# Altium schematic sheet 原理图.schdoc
size 292 x 204 mm; Device: A_A4; Symbol: A_A4; Name: A_A4; @Project Name: MYNOVA-射频管家; REV: 1.0; Date: 2024/03/05; Sheet: 1/1; Draw By: Tomosawa; Company: MYNOVA; Convert to PCB: yes; Add into BOM: yes
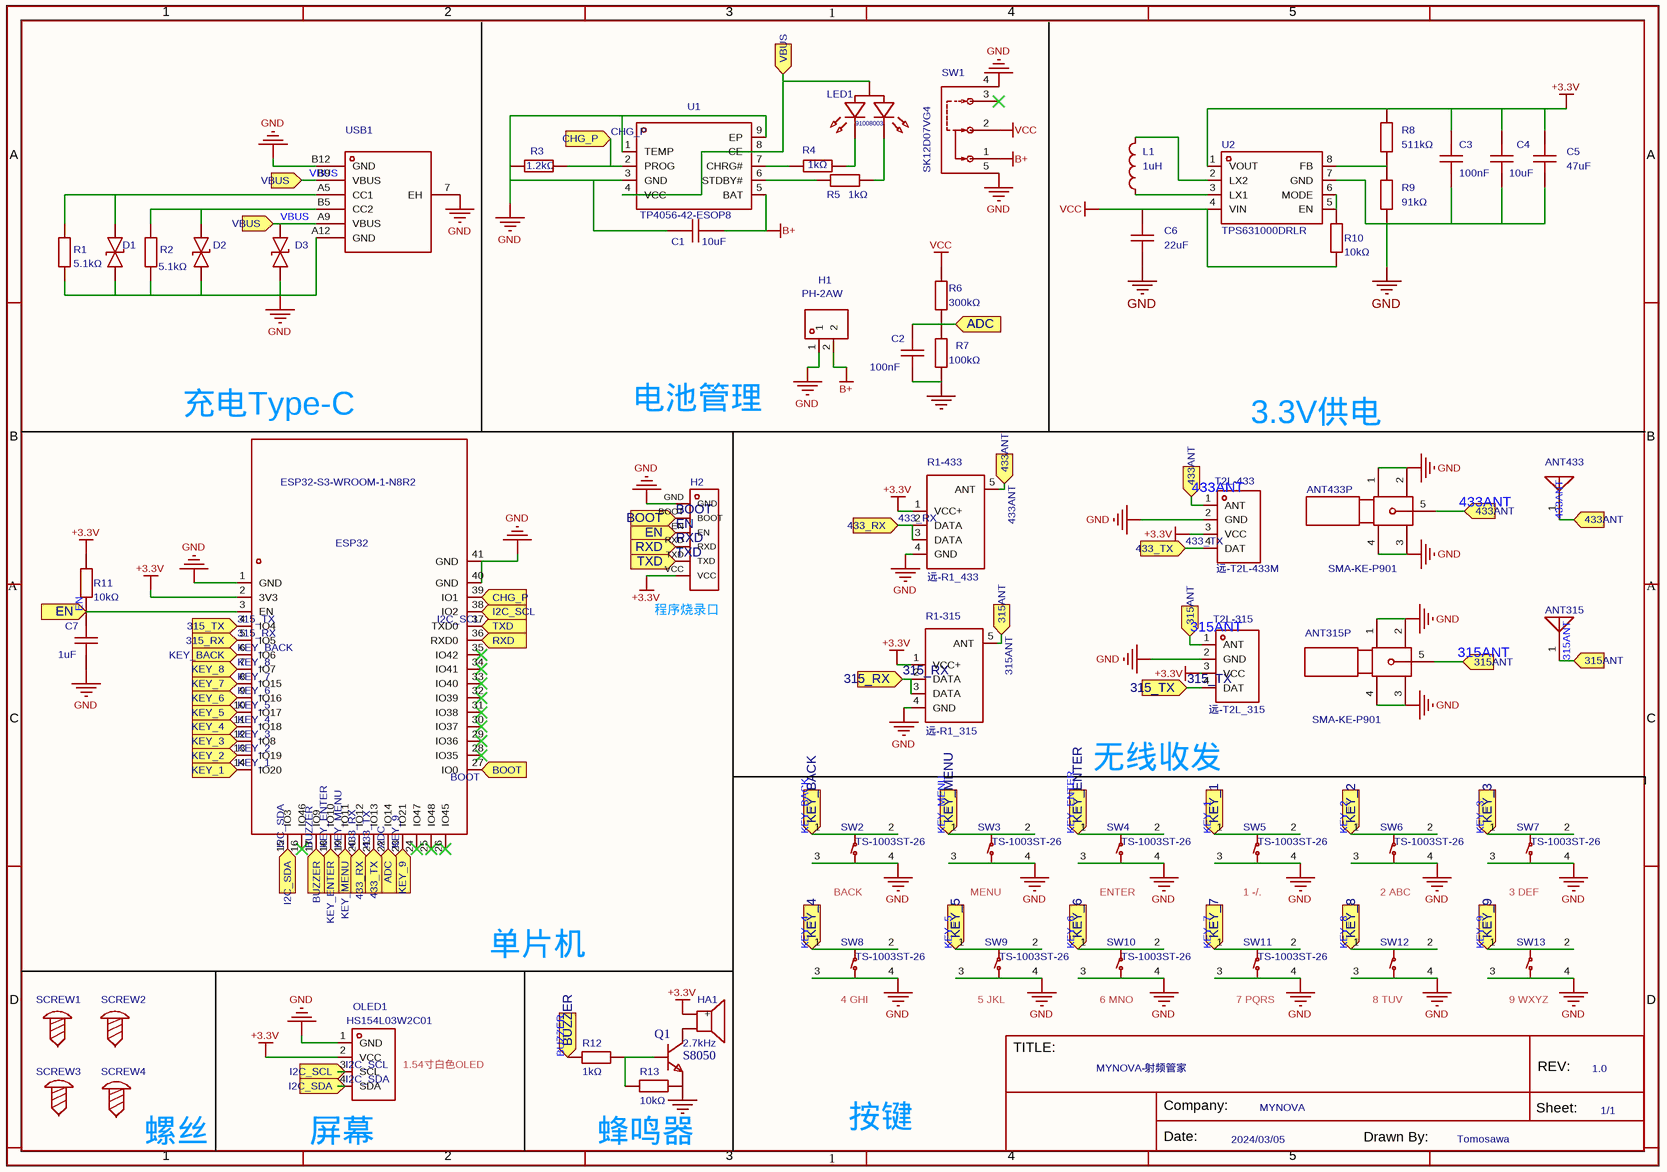
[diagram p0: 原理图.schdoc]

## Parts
ANT315  (no value)  [SMD-ANT-315]
ANT315P  SMA-KE-P901  [SMA-TH_SMA-KE-P901]
ANT433  (no value)  [SMD-ANT-433]
ANT433P  SMA-KE-P901  [SMA-TH_SMA-KE-P901]
C1  10uF  [C0603]
C2  100nF  [C0603]
C3  100nF  [C0603]
C4  10uF  [C0603]
C5  47uF  [C0603]
C6  22uF  [C0603]
C7  1uF  [C0603]
D1  LESD5D5.0CT1G  [SOD-523_L1.2-W0.8-LS1.6-BI]  (value not drawn)
D2  LESD5D5.0CT1G  [SOD-523_L1.2-W0.8-LS1.6-BI]  (value not drawn)
D3  LESD5D5.0CT1G  [SOD-523_L1.2-W0.8-LS1.6-BI]  (value not drawn)
ESP32  ESP32-S3-WROOM-1-N8R2  [WIRELM-SMD_ESP32-S3-WROOM-1]
H1  PH-2AW  [CONN-TH_PH-2AW_C2908634]
H2  (no value)  [6PIN-2MM-UART]
HA1  2.7kHz  [BUZ-TH_BD9.0-P5.00-D0.6-FD]
L1  1uH  [L1008]
LED1  91008003  [LED-TH_3P-BD3.8-P2.54-BI]
OLED1  HS154L03W2C01  [OLED-TH_-4P-L42.4-W38.0-P2.54]
Q1  S8050  [SOT-23-3_L2.9-W1.3-P1.90-LS2.4-BR]
R1  5.1kΩ  [R0603]
R1-315  远-R1_315  [COMM-SMD_YUAN-R1-315]
R1-433  远-R1_433  [COMM-SMD_YUAN-R1-433]
R2  5.1kΩ  [R0603]
R3  1.2kΩ  [R0603]
R4  1kΩ  [R0603]
R5  1kΩ  [R0603]
R6  300kΩ  [R0603]
R7  100kΩ  [R0603]
R8  511kΩ  [R0603]
R9  91kΩ  [R0603]
R10  10kΩ  [R0603]
R11  10kΩ  [R0603]
R12  1kΩ  [R0603]
R13  10kΩ  [R0603]
SCREW1  (no value)  [M2螺丝]
SCREW2  (no value)  [M2螺丝]
SCREW3  (no value)  [M2螺丝]
SCREW4  (no value)  [M2螺丝]
SW1  SK12D07VG4  [SW-TH_SK12D07VG4]
SW2  TS-1003ST-26  [SW-SMD-1212KEY]
SW3  TS-1003ST-26  [SW-SMD-1212KEY]
SW4  TS-1003ST-26  [SW-SMD-1212KEY]
SW5  TS-1003ST-26  [SW-SMD-1212KEY]
SW6  TS-1003ST-26  [SW-SMD-1212KEY]
SW7  TS-1003ST-26  [SW-SMD-1212KEY]
SW8  TS-1003ST-26  [SW-SMD-1212KEY]
SW9  TS-1003ST-26  [SW-SMD-1212KEY]
SW10  TS-1003ST-26  [SW-SMD-1212KEY]
SW11  TS-1003ST-26  [SW-SMD-1212KEY]
SW12  TS-1003ST-26  [SW-SMD-1212KEY]  (value not drawn)
SW13  TS-1003ST-26  [SW-SMD-1212KEY]  (value not drawn)
T2L-315  远-T2L_315  [WIRELM-SMD_L10.5-W8.3-P2.54]
T2L-433  远-T2L-433M  [WIRELM-SMD_L10.5-W8.3-P2.54]
U1  TP4056-42-ESOP8  [ESOP-8_L4.9-W3.9-P1.27-LS6.0-BL-EP]
U2  TPS631000DRLR  [SOT-583-8_L2.1-W1.2-P0.50-LS1.6-BL]
USB1  TYPE-C 6P(073)  [TYPE-C-SMD_TYPE-C-6P]  (value not drawn)

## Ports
315_RX (in), 315_TX (in), 315ANT (in), 433_RX (in), 433_TX (in), 433ANT (in), ADC (in), BOOT (in), BUZZER (in), CHG_P (in), EN (in), I2C_SCL (in), I2C_SDA (in), KEY_1 (in), KEY_2 (in), KEY_3 (in), KEY_4 (in), KEY_5 (in), KEY_6 (in), KEY_7 (in), KEY_8 (in), KEY_9 (in), KEY_BACK (in), KEY_ENTER (in), KEY_MENU (in), RXD (in), TXD (in), VBUS (in)

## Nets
+3.3V: C3.2 C4.2 C5.2 ESP32.2(3V3) H2.VCC HA1.1(+) OLED1.2(VCC) R1-315.1(VCC+) R1-433.1(VCC+) R8.2 R11.1 T2L-315.3(VCC) T2L-433.3(VCC) U2.1(VOUT)
B+: C1.1 H1.2 SW1.1 U1.5(BAT)
GND: ANT315P.1 ANT315P.2 ANT315P.3 ANT315P.4 ANT433P.1 ANT433P.2 ANT433P.3 ANT433P.4 C1.2 C2.1 C3.1 C4.1 C5.1 C6.1 C7.1 D1.2 D2.2 D3.2 ESP32.1(GND) ESP32.40(GND) ESP32.41(GND) H1.1 H2.GND OLED1.1(GND) Q1.2(E) R1.2 R1-315.4(GND) R1-433.4(GND) R2.2 R3.1 R7.1 R9.1 R13.2 SW1.4 SW1.5 SW2.3(C) SW2.4(D) SW3.3(C) SW3.4(D) SW4.3(C) SW4.4(D) SW5.3(C) SW5.4(D) SW6.3(C) SW6.4(D) SW7.3(C) SW7.4(D) SW8.3(C) SW8.4(D) SW9.3(C) SW9.4(D) SW10.3(C) SW10.4(D) SW11.3(C) SW11.4(D) SW12.3(C) SW12.4(D) SW13.3(C) SW13.4(D) T2L-315.2(GND) T2L-433.2(GND) U1.1(TEMP) U1.3(GND) U1.9(EP) U2.7(GND) USB1.7(EH) USB1.A12(GND) USB1.B12(GND)
VCC: C6.2 R6.2 R10.2 SW1.2 U2.4(VIN)
315_RX: ESP32.5(IO5) R1-315.2(DATA) R1-315.3(DATA) ; port 315_RX
315_TX: ESP32.4(IO4) T2L-315.4(DAT) ; port 315_TX
315ANT: ANT315.1 ANT315P.5 R1-315.5(ANT) T2L-315.1(ANT) ; port 315ANT
433_RX: ESP32.20(IO12) R1-433.2(DATA) R1-433.3(DATA) ; port 433_RX
433_TX: ESP32.21(IO13) T2L-433.4(DAT) ; port 433_TX
433ANT: ANT433.1 ANT433P.5 R1-433.5(ANT) T2L-433.1(ANT) ; port 433ANT
ADC: C2.2 ESP32.22(IO14) R6.1 R7.2 ; port ADC
BOOT: ESP32.27(IO0) H2.BOOT ; port BOOT
BUZZER: ESP32.17(IO9) R12.1 ; port BUZZER
CHG_P: ESP32.39(IO1) R3.2 U1.2(PROG) ; port CHG_P
EN: C7.2 ESP32.3(EN) H2.EN R11.2 ; port EN
I2C_SCL: ESP32.38(IO2) OLED1.3(SCL) ; port I2C_SCL
I2C_SDA: ESP32.15(IO3) OLED1.4(SDA) ; port I2C_SDA
KEY_1: ESP32.14(IO20) SW5.1(A) SW5.2(B) ; port KEY_1
KEY_2: ESP32.13(IO19) SW6.1(A) SW6.2(B) ; port KEY_2
KEY_3: ESP32.12(IO8) SW7.1(A) SW7.2(B) ; port KEY_3
KEY_4: ESP32.11(IO18) SW8.1(A) SW8.2(B) ; port KEY_4
KEY_5: ESP32.10(IO17) SW9.1(A) SW9.2(B) ; port KEY_5
KEY_6: ESP32.9(IO16) SW10.1(A) SW10.2(B) ; port KEY_6
KEY_7: ESP32.8(IO15) SW11.1(A) SW11.2(B) ; port KEY_7
KEY_8: ESP32.7(IO7) SW12.1(A) SW12.2(B) ; port KEY_8
KEY_9: ESP32.23(IO21) SW13.1(A) SW13.2(B) ; port KEY_9
KEY_BACK: ESP32.6(IO6) SW2.1(A) SW2.2(B) ; port KEY_BACK
KEY_ENTER: ESP32.18(IO10) SW4.1(A) SW4.2(B) ; port KEY_ENTER
KEY_MENU: ESP32.19(IO11) SW3.1(A) SW3.2(B) ; port KEY_MENU
RXD: ESP32.36(RXD0) H2.RXD ; port RXD
TXD: ESP32.37(TXD0) H2.TXD ; port TXD
VBUS: D3.1 LED1.2(K) U1.4(VCC) U1.8(CE) USB1.A9(VBUS) USB1.B9(VBUS) ; port VBUS
NetD1_1: D1.1 R1.1 USB1.A5(CC1)
NetD2_1: D2.1 R2.1 USB1.B5(CC2)
NetHA1_2: HA1.2 Q1.3(C)
NetL1_1: L1.1 U2.3(LX1)
NetL1_2: L1.2 U2.2(LX2)
NetLED1_1: LED1.1(A) R5.1
NetLED1_3: LED1.3(A) R4.1
NetQ1_1: Q1.1(B) R12.2 R13.1
NetR4_2: R4.2 U1.7(CHRG#)
NetR5_2: R5.2 U1.6(STDBY#)
NetR8_1: R8.1 R9.2 U2.8(FB)
NetR10_1: R10.1 U2.5(EN) U2.6(MODE)

Not connected (* = marked no-connect by the designer): ESP32 16(IO46)* 24(IO47)* 25(IO48)* 26(IO45)* 28(IO35)* 29(IO36)* 30(IO37)* 31(IO38)* 32(IO39)* 33(IO40)* 34(IO41)* 35(IO42)*; SCREW1 1; SCREW2 1; SCREW3 1; SCREW4 1; SW1 3*

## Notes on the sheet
- 充电Type-C
- 电池管理
- 3.3V供电
- (near H2) 程序烧录口
- 无线收发
- (near SW2) BACK
- (near SW3) MENU
- (near SW4) ENTER
- (near SW5) 1 -/.
- (near SW6) 2 ABC
- (near SW7) 3 DEF
- 单片机
- (near SW8) 4 GHI
- (near SW9) 5 JKL
- (near SW10) 6 MNO
- (near SW11) 7 PQRS
- (near SW12) 8 TUV
- (near SW13) 9 WXYZ
- (near OLED1) 1.54寸白色OLED
- (near SCREW4) 螺丝
- (near OLED1) 屏幕
- (near R13) 蜂鸣器
- 按键

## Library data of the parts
ANT315 = ANT-315MHz: 315MHz的天线; Manufacturer: DreamLNK(骏晔科技); Manufacturer Part: T16-315M; Connector Type: 板端; Interface Type: 内针; Number of Ports: 1; Interface Diameter: 5.35mm; Frequency-Max: 3GHz; RF Series: RP-SMA; Impedance: 50Ω; Style: 偏脚; Origin Footprint: 433MHZ天线; Convert to PCB: yes; ModelId: 24642a22739b4c8ba708c6c7ad2992f36727c7c5e668472884194f91f9f46558; ModelName: ANT315; ModelTransform: 208.66,1336.26,208.66,-90,90,0,0,-472.44,102.36
ANT315P = SMA-KE-P901: 连接器类型:板端;接口类型:内针;端口数量:1;接口直径:5.35mm;接口长度/高度:-;频率-最大值:3GHz;射频系列:RP-SMA;阻抗:50Ω;样式:偏脚;工作温度范围:-55℃~+125℃;; Manufacturer: DreamLNK(骏晔科技); Origin Footprint: 315MHZ天线; Convert to PCB: yes; ModelId: 7448f774b1b34b0fa378ce7b88059936; ModelTransform: 249.9995,448.818,0,180,0,0,0,192.441,-110.236; Connector Type: 板端; Interface Type: 内针; Number of Ports: 1; Interface Diameter: 5.35mm; Frequency-Max: 3GHz; RF Series: RP-SMA; Impedance: 50Ω; Style: 偏脚
ANT433 = ANT-433MHz: 433MHz的天线; Manufacturer: Vollgo(沃进); Manufacturer Part: VG433SNX39-6W3; Connector Type: 板端; Interface Type: 内针; Number of Ports: 1; Interface Diameter: 5.35mm; Frequency-Max: 3GHz; RF Series: RP-SMA; Impedance: 50Ω; Style: 偏脚; Origin Footprint: 433MHZ天线; Symbol: ANT-315MHz; Convert to PCB: yes; Antenna Type: 弹簧天线; Central Frequency: 433MHz; Peak Gain: 2.5dBi; Polarization Type: 垂直; VSWR: 2; ModelId: 49afb8bdb95845d6999d595e8683600d6727c7c5e668472884194f91f9f46558; ModelName: ANT433; ModelTransform: 228.35,228.35,1452.47,90,0,90,-59.06,0,118.11
ANT433P = SMA-KE-P901: 连接器类型:板端;接口类型:内针;端口数量:1;接口直径:5.35mm;接口长度/高度:-;频率-最大值:3GHz;射频系列:RP-SMA;阻抗:50Ω;样式:偏脚;工作温度范围:-55℃~+125℃;; Manufacturer: DreamLNK(骏晔科技); Origin Footprint: 433MHZ天线; Convert to PCB: yes; ModelId: 7448f774b1b34b0fa378ce7b88059936; ModelTransform: 249.9995,448.818,0,180,0,0,0,192.441,-110.236; Connector Type: 板端; Interface Type: 内针; Number of Ports: 1; Interface Diameter: 5.35mm; Frequency-Max: 3GHz; RF Series: RP-SMA; Impedance: 50Ω; Style: 偏脚
C1 = CL10A106KP8NNNC: 容值:10uF;精度:±10%;额定电压:10V;材质(温度系数):X5R;; Manufacturer: SAMSUNG(三星); Symbol: CL21A106KAYNNNE; Convert to PCB: yes; ModelId: ac125912035d415993ca9572d50418b1; ModelName: C0603_L1.6-W0.8-H0.8; ModelTransform: 62.992,31.496,0,0,0,0,0,0,0; Tolerance: ±10%; Voltage Rated: 10V; Temperature Coefficient: X5R
C2 = CC0603KRX7R9BB104: 容值:100nF;精度:±10%;额定电压:50V;材质(温度系数):X7R;; Manufacturer: YAGEO(国巨); Symbol: Capacitance; AddInBom: yes; ModelId: ac125912035d415993ca9572d50418b1; ModelName: C0603_L1.6-W0.8-H0.8; ModelTransform: 62.992,31.496,0,0,0,0,0,0,0; Tolerance: ±10%; Voltage Rated: 50V; Temperature Coefficient: X7R
C3 = CC0603KRX7R9BB104: 容值:100nF;精度:±10%;额定电压:50V;材质(温度系数):X7R;; Manufacturer: YAGEO(国巨); Symbol: Capacitance; 3D Model: ac125912035d415993ca9572d50418b1; 3D Model Transform: 62.992,31.496,0,0,0,0,0,0,0; Tolerance: ±10%; Voltage Rated: 50V; Temperature Coefficient: X7R; AddInBom: yes; ModelName: C0603_L1.6-W0.8-H0.8
C4 = CL10A106KP8NNNC: 容值:10uF;精度:±10%;额定电压:10V;温度系数:X5R;; Manufacturer: SAMSUNG(三星); Add into BOM: yes; 3D Model: ac125912035d415993ca9572d50418b1; 3D Model Transform: 62.992,31.496,0,0,0,0,0,0,0; Tolerance: ±10%; Temperature Coefficient: X5R; Voltage Rating: 10V; ModelName: C0603_L1.6-W0.8-H0.8
C5 = CL10A476MQ8QRNC: 容值:47uF;精度:±20%;额定电压:6.3V;温度系数:X5R;; Manufacturer: SAMSUNG(三星); Add into BOM: yes; 3D Model: ac125912035d415993ca9572d50418b1; 3D Model Transform: 62.992,31.496,0,0,0,0,0,0,0; Tolerance: ±20%; Voltage Rating: 6.3V; Temperature Coefficient: X5R; ModelName: C0603_L1.6-W0.8-H0.8
C6 = CL10A226MP8NUNE: 容值:22uF;精度:±20%;额定电压:10V;温度系数:X5R;; Manufacturer: SAMSUNG(三星); Add into BOM: yes; 3D Model: ac125912035d415993ca9572d50418b1; 3D Model Transform: 62.992,31.496,0,0,0,0,0,0,0; Tolerance: ±20%; Voltage Rating: 10V; Temperature Coefficient: X5R; ModelName: C0603_L1.6-W0.8-H0.8
C7 = CC0603KRX5R8BB105: 容值:1uF;精度:±10%;额定电压:25V;材质(温度系数):X5R;; Manufacturer: YAGEO(国巨); Symbol: Capacitance; 3D Model: ac125912035d415993ca9572d50418b1; 3D Model Transform: 62.992,31.496,0,0,0,0,0,0,0; Tolerance: ±10%; Voltage Rated: 25V; Temperature Coefficient: X5R; AddInBom: yes; ModelName: C0603_L1.6-W0.8-H0.8
D1-D3 = LESD5D5.0CT1G: 极性:Bidirectional;反向关断电压（典型值）:5V;击穿电压（最小值）:5.6V;箝位电压:18.6V;峰值脉冲电流（10/1000us）:9.4A (8/20us);; Manufacturer: LRC(乐山无线电); 3D Model: 8f56a03db567494d8f4c9d12aa52a741; 3D Model Transform: 62.992,31.496,0,0,0,0,0,0,0; Voltage - Reverse Standoff (Typ): 5V; Voltage - Breakdown (Min): 5.6V; Voltage - Clamping (Max) @ Ipp: 18.6V; AddInBom: yes; ModelName: SOD-523_L1.2-W0.8-H0.7-LS1.6
ESP32 = ESP32-S3-WROOM-1-N8R2: 核心芯片:ESP32-S3芯片;频率:2.4GHz;; Manufacturer: ESPRESSIF(乐鑫); Symbol: ESP32-S3-WROOM-1(N16R8); Add into BOM: yes; 3D Model: 481f5bdfc076422c9bb3c23c3ada9c17; 3D Model Transform: 708.73866,1003.97437,0,0,0,0,0,143.7,0; Interface Type: SPI；I2S；USB；I2C；UART; Value: 2.4GHz
H1 = PH-2AW_C2908634: 插针结构:1x2P;间距:2mm;安装方式:弯插;参考系列:PH;总PIN数:2P;排数:1;每排PIN数:2;行距:-;额定电流:2A;触头材质:黄铜;触头镀层:锡;工作温度范围:-20℃~+85℃;; Manufacturer: HCTL(华灿天禄); Origin Footprint: HDR-F-2.54_1X2; Symbol: PH-2A_C2908623; Convert to PCB: yes; ModelId: ca8868ea066f4ceca9cfafa41270f7a2; ModelTransform: 236.22,261.8105,0,0,0,0,0,122.047,-118.11; Pins Structure: 1x2P; Pitch: 2mm; Reference Series: PH; Number of PINs Per Row: 2; Current Rating (Max): 2A
H2 = 6PIN-2MM-UART: 串口烧录接口; Add into BOM: no; Symbol: PZ200V-11-06P; ConvertToPcb: yes; Pin Structure: 1x6P; Pitch: 2mm; Circluar Pins/Square Pins: 方针
HA1 = YS-MBZ9055DYB03: 驱动方式:有源(内含驱动线路);构造类型:电磁式;频率:2.7kHz;声压(SPL):85dB@3V,10cm;; Manufacturer: Fengming(锋鸣电子); Symbol: TMB12A03; AddInBom: yes; ModelId: 13273335caac486e928bafb4d9fdf12d; ModelName: BUZ-TH_D9.0-H5.5-P5.0; ModelTransform: 354.33,354.33,0,90,0,0,-0.005,0,-177.165; Technology Type: 电磁式; Operating Voltage: 2V~5V
L1 = FTM252012S1R0MCTA: 电感值:1uH;精度:±20%;额定电流:4.3A;饱和电流(Isat):4.9A;; Manufacturer: cjiang(长江微电); Add into BOM: yes; 3D Model: d662a90583c04d9889a0ce9dce974838; 3D Model Transform: 98.425,78.74,0,0,0,0,0,0,0; Tolerance: ±20%; Current Rating: 4.3A; Current - Saturation(Isat): 4.9A; DC Resistance(DCR): 37mΩ
LED1 = 91008003: 发光颜色:红色,翠绿色;二极管配置:共阳极;透镜颜色:透明透镜;; Manufacturer: 深宏电子; Lamp Holder Type: 3mm圆形灯头; Power Dissipation: 60mW; Forward Current: 20mA; Dominant Wavelength: 624nm; Peak Wavelength: 632nm; Viewing Angle: 40°; Origin Footprint: LED-SMD_L1.7-W0.6-RD; Convert to PCB: yes; ModelId: 2ffa1f55fde94da3bd1475be65d6aa87; ModelName: LED-TH_3P-BD3.8-H5.3-P2.54; ModelTransform: 219.6846,149.563,0,0,0,0,2.008,0,-137.795; Emitted Color: 红色,翠绿色; Diode Configuration: 共阳极; Lens Color: 透明透镜
OLED1 = HS154L03W2C01: 主控芯片:SSD1309;接口类型:I2C;尺寸(inch):1.54;; Manufacturer: HS(汉昇); Origin Footprint: 0.96OLED_4P去孔; Convert to PCB: yes; ModelId: aa861fa4eb4a4bd2a39608f58e47f232; ModelName: OLED-TH_4P-L42.4-W38.0-P2.54; ModelTransform: 1669.288,1496.06,0,0,0,0,0,-673.03,-118.11; Interface Type: I2C
Q1 = S8050_C2891804: 晶体管类型:NPN;集电极电流(Ic):500mA;集射极击穿电压(Vceo):25V;功率(Pd):300mW;; Manufacturer: YONGYUTAI(永裕泰); Origin Footprint: SOT23; AddInBom: yes; ModelId: c62791f0466c4ae2a892c056b845b0ca; ModelName: SOT-23-3P_L2.9-W1.3-H1.0-LS2.4-P0.95; ModelTransform: 98.425,114.173,0,180,0,0,0.0005,-0.0005,0; Transistor Type: NPN; Collector Current (Ic): 500mA; Collector-Emitter Breakdown Voltage (Vceo): 25V; Power Dissipation (Pd): 300mW; Collector Cut-Off Current (Icbo): 1uA; Collector-Emitter Saturation Voltage (VCE(sat)@Ic,Ib): 500mV@500mA,50mA
R1 R2 = 0603WAF5101T5E_1: 电阻类型:厚膜电阻;阻值:5.1kΩ;精度:±1%;功率:100mW;最大工作电压:75V;温度系数:±100ppm/℃;; Manufacturer: UNI-ROYAL(厚声); Add into BOM: yes; 3D Model: fc143cca1e79419f9cd78b61e9279f08; 3D Model Transform: 31.8897,63.7794,0,90,0,0,0,0,0; Tolerance: ±1%; Power(Watts): 100mW; Overload Voltage (Max): 75V
R1-315 = 远-R1_315: 无线接收模块; Manufacturer: 蜂鸟无线; Add into BOM: yes; 3D Model: ae34fbea77134a96b62d70dde6281d40; 3D Model Transform: 866.14,354.33,0,0,0,0,-2.126,7.874,0; ModelName: COMM-SMD_YUAN-R1-433
R1-433 = 远-R1_433: Manufacturer: 蜂鸟无线; Add into BOM: yes; 3D Model: ae34fbea77134a96b62d70dde6281d40; 3D Model Transform: 866.14,354.33,0,0,0,0,-2.126,7.874,0
R3 = 0603WAF1201T5E: 电阻类型:厚膜电阻;阻值:1.2kΩ;精度:±1%;功率:100mW;最大工作电压:75V;温度系数:±100ppm/℃;; Manufacturer: UNI-ROYAL(厚声); Convert to PCB: yes; ModelId: fc143cca1e79419f9cd78b61e9279f08; ModelTransform: 31.8897,63.7794,0,90,0,0,0,0,0; Tolerance: ±1%; Power(Watts): 100mW; Overload Voltage (Max): 75V
R4 R5 = RC0603FR-071KL: 电阻类型:厚膜电阻;阻值:1kΩ;精度:±1%;功率:100mW;最大工作电压:75V;温度系数:±100ppm/℃;; Manufacturer: YAGEO(国巨); Convert to PCB: yes; ModelId: fc143cca1e79419f9cd78b61e9279f08; ModelTransform: 31.8897,63.7794,0,90,0,0,0,0,0; Tolerance: ±1%; Power(Watts): 100mW; Overload Voltage (Max): 75V
R6 = 0603WAF3003T5E: 电阻类型:厚膜电阻;阻值:300kΩ;精度:±1%;功率:100mW;最大工作电压:75V;温度系数:±100ppm/℃;; Manufacturer: UNI-ROYAL(厚声); Symbol: 电阻; AddInBom: yes; ModelId: fc143cca1e79419f9cd78b61e9279f08; ModelTransform: 31.8897,63.7794,0,90,0,0,0,0,0; Tolerance: ±1%; Power(Watts): 100mW; Overload Voltage (Max): 75V
R7 = 0603WAF1003T5E: 电阻类型:厚膜电阻;阻值:100kΩ;精度:±1%;功率:100mW;最大工作电压:75V;温度系数:±100ppm/℃;; Manufacturer: UNI-ROYAL(厚声); Symbol: 电阻; AddInBom: yes; ModelId: fc143cca1e79419f9cd78b61e9279f08; ModelTransform: 31.8897,63.7794,0,90,0,0,0,0,0; Tolerance: ±1%; Power(Watts): 100mW; Overload Voltage (Max): 75V
R8 = 0603WAF5113T5E: 电阻类型:厚膜电阻;阻值:511kΩ;精度:±1%;功率:100mW;工作电压:75V;温度系数:±100ppm/℃;; Manufacturer: UNI-ROYAL(厚声); Add into BOM: yes; 3D Model: fc143cca1e79419f9cd78b61e9279f08; 3D Model Transform: 31.8897,63.7794,0,90,0,0,0,0,0; Tolerance: ±1%; Power(Watts): 100mW; Voltage-Supply(Max): 75V
R9 = 0603WAF9102T5E: 电阻类型:厚膜电阻;阻值:91kΩ;精度:±1%;功率:100mW;工作电压:75V;温度系数:±100ppm/℃;; Manufacturer: UNI-ROYAL(厚声); Add into BOM: yes; 3D Model: fc143cca1e79419f9cd78b61e9279f08; 3D Model Transform: 31.8897,63.7794,0,90,0,0,0,0,0; Tolerance: ±1%; Power(Watts): 100mW; Voltage-Supply(Max): 75V
R10 R11 = 0603WAF1002T5E: 电阻类型:厚膜电阻;阻值:10kΩ;精度:±1%;功率:100mW;最大工作电压:75V;温度系数:±100ppm/℃;; Manufacturer: UNI-ROYAL(厚声); Symbol: RC0603FR-071KL; Add into BOM: yes; 3D Model: fc143cca1e79419f9cd78b61e9279f08; 3D Model Transform: 31.8897,63.7794,0,90,0,0,0,0,0; Tolerance: ±1%; Power(Watts): 100mW; Overload Voltage (Max): 75V
R12 = RC0603FR-071KL: 电阻类型:厚膜电阻;阻值:1kΩ;精度:±1%;功率:100mW;最大工作电压:75V;温度系数:±100ppm/℃;; Manufacturer: YAGEO(国巨); Symbol: 电阻; AddInBom: yes; ModelId: fc143cca1e79419f9cd78b61e9279f08; ModelTransform: 31.8897,63.7794,0,90,0,0,0,0,0; Tolerance: ±1%; Power(Watts): 100mW; Overload Voltage (Max): 75V
R13 = 0603WAF1002T5E: 电阻类型:厚膜电阻;阻值:10kΩ;精度:±1%;功率:100mW;最大工作电压:75V;温度系数:±100ppm/℃;; Manufacturer: UNI-ROYAL(厚声); Symbol: 电阻; AddInBom: yes; ModelId: fc143cca1e79419f9cd78b61e9279f08; ModelTransform: 31.8897,63.7794,0,90,0,0,0,0,0; Tolerance: ±1%; Power(Watts): 100mW; Overload Voltage (Max): 75V
SCREW1-SCREW4 = M2螺丝: ConvertToPcb: yes; SymbolName: 螺丝孔
SW1 = SK12D07VG4: 电路结构:单刀双掷;安装方式:侧插;额定电流(DC):500mA;额定电压(DC):50V;额定电流(AC):-;额定电压(AC):-;机械寿命:5千次;; Manufacturer: SHOU HAN(首韩); Origin Footprint: SK-22D07; Convert to PCB: yes; ModelId: 773c51563d484e3a80810244c5d56a16; ModelName: SW-TH_L8.7-W4.4-H4.0-P2.0; ModelTransform: 338.582,279.527,0,0,0,0,0,-51.181,-125.984; Circuit: 单刀双掷; Actuator Style: 矩形柱状; Pin Style: PC引脚; Switch Height: 8.8mm; Current Rating (DC): 500mA; Voltage Rating (DC): 50V; Mechanical Life: 5千次
SW2-SW13 = TS-1003ST-26: 电路结构:单刀单掷;按钮形状:矩形按钮;安装方式:立贴;开关长度:12mm;开关宽度:12mm;开关高度:7.3mm;触点电流:50mA;额定电压(DC):12V;带灯:-;机械寿命:-;; Manufacturer: XUNPU(讯普); Symbol: TS665CJ; AddInBom: yes; ModelId: b6bb9c75b6a841fe940fb934d0e410a7; ModelName: SW-SMD_4P-L12.0-W12.0-H14-P5.00-LS15.2; ModelTransform: 598.424,472.44,0,0,0,0,-0.005,-0.591,0; Circuit: 单刀单掷; Actuator Style: 矩形按钮; Switch Length: 12mm; Switch Height: 7.3mm; Contact Current: 50mA; Voltage Rating (DC): 12V
T2L-315 = 远-T2L_315: 无线发射模块 远-T2L是一款小体积、远距离的ASK/OOK低电压发射模块。该模块采用高性能RF集成芯片，内置谐波抑制电路，具有超小体积、低功耗、大功率、高稳定性、高性价比等特点，专为3V电池系统设计。; Manufacturer: 蜂鸟无线; Symbol: YUAN-T2L_315; Add into BOM: yes; 3D Model: afb9c14227a34ca680ace824a64fbb5e; 3D Model Transform: 413.385,326.771,0,0,0,0,0,142.086,0
T2L-433 = 远-T2L-433M: 远-T2L是一款小体积、远距离的ASK/OOK低电压发射模块。该模块采用高性能RF集成芯片，内置谐波抑制电路，具有超小体积、低功耗、大功率、高稳定性、高性价比等特点，专为3V电池系统设计。; Manufacturer: 蜂鸟无线; Add into BOM: yes; 3D Model: afb9c14227a34ca680ace824a64fbb5e; 3D Model Transform: 413.385,326.771,0,0,0,0,0,142.086,0
U1 = TP4056-42-ESOP8: 锂电池充电芯片 42代表电池满电电压4.2V。; Manufacturer: TOPPOWER(南京拓微); Symbol: TP4056; Convert to PCB: yes; ModelId: d3e00daa36c445139c055a3b9efb85d2; ModelName: ESOP-8_L4.9-W3.9-H1.6-LS6.0-P1.27; ModelTransform: 240.157,192.913,0,90,0,0,0,0,0
U2 = TPS631000DRLR: 功能类型:升降压型;工作电压:1.6V~5.5V;输出电压:1.2V~5.3V;输出电流:2A;输出类型:可调;; Manufacturer: TI(德州仪器); Add into BOM: yes; 3D Model: 14eb3df1056d4df2aac7ceeb7e81e738; 3D Model Transform: 82.677,62.992,0,0,0,0,0,0,0; Function: 升降压型; Output Current: 2A; Frequency - Switching: 2.2MHz; Topology: 降压-升压式; Quiescent Current: 8uA; Switch tube (built-in/external): 内置; Output Type: 可调
USB1 = TYPE-C 6P(073): 连接器类型:Type-C;标准:-;公母:母;端口数量:1;触点数量:6P;安装方式:卧贴;额定电流 - 电源:5A;工作温度范围:-25℃~+85℃;; Manufacturer: SHOU HAN(首韩); 3D Model: 3770c5585474407db939b2377e27177a; 3D Model Transform: 351.9678,267.716,0,180,0,0,0,-45.766,-39.37; Gender: 母; Number of Ports: 1; Current Rating - Power (Max): 5A; AddInBom: yes; ModelName: TYPE-C-SMD_6P-L8.9-W6.8-H3.2-P1.00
